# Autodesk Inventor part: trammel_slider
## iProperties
Created: 2008-11
Part Number: trammel_slider
Document SubType Name: Modeling
Designer: Lochan
Density: 1 g/cm^3
Author: Lochan
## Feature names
1. Extrusion1
2. Extrusion2
